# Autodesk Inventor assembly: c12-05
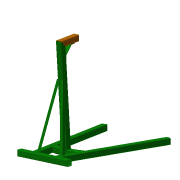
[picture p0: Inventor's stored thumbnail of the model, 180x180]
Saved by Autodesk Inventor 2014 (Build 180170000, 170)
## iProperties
Created: 2011-01
Part Number: c12-05
Document SubType Name: Assembly
Designer: Thom Tremblay
_SolveAssemblyDoc: Frame Generator Solve Assembly
_Version: 15.0.0
Author: Thom Tremblay
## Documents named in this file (3)
- C:\Inventor 2014 Essentials\Assemblies\Chapter 12\c12-05.iam
- C:\Inventor 2014 Essentials\Assemblies\Chapter 12\Frame\Frame c12-05.iam
- C:\Inventor 2014 Essentials\Parts\Chapter 12\c12-02.ipt
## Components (2 placed, 2 different names)
1. c12-02:1
2. Frame c12-05:1 [sub-assembly]
